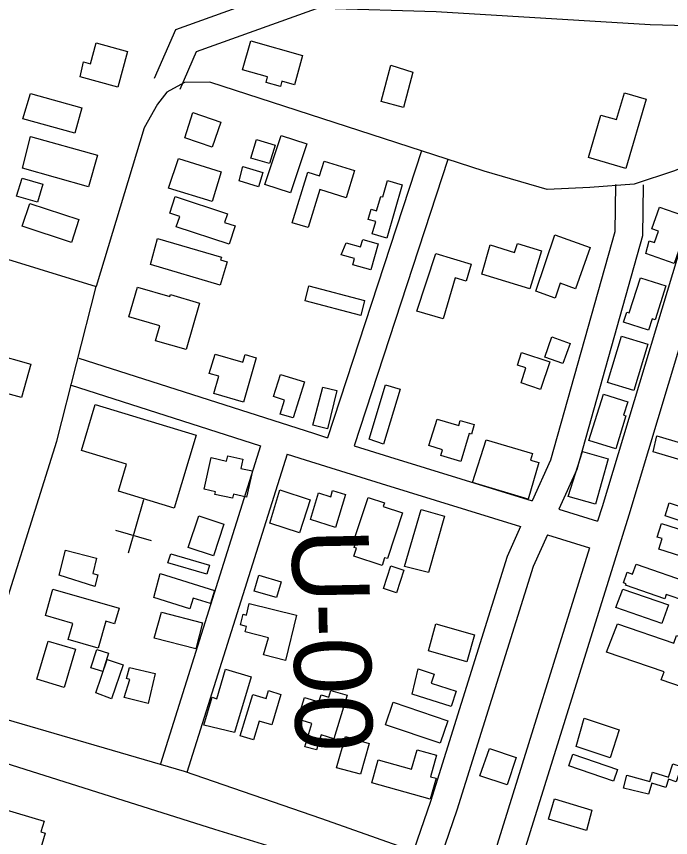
# Model space of a CAD drawing. Extents: x 3324125 to 3362000, y 600753 to 626151.
# Drawn here: x 3340066 to 3340770, y 607880 to 608764 of the extents above; entities that cross this region are included whole.
import ezdxf

# ---------------------------------------------------------------- set-up
doc = ezdxf.new("R2010")
doc.units = 0
for name, color, linetype in [('V-BLDG-OTLN', 7, 'Continuous'), ('V-LEVE-TOET', 7, 'Continuous'), ('V-RIVR-RANG-IDEN', 7, 'Continuous'), ('V-ROAD-CNTR', 7, 'Continuous'), ('V-SITE-OTLN', 7, 'Continuous')]:
    doc.layers.add(name, color=color, linetype=linetype)

msp = doc.modelspace()

# ---------------------------------------------------------------- linework, layer by layer
at = {"layer": 'V-BLDG-OTLN'}
for points in [[(3340134.5, 608698.92), (3340138.17, 608715.1), (3340145.47, 608713.1), (3340151.59, 608735.46), (3340185.35, 608726.22), (3340174.87, 608687.89)], [(3340318.34, 608737.8), (3340374.03, 608721.92), (3340365.08, 608690.53), (3340351.64, 608694.36), (3340350, 608688.63), (3340334.61, 608693.02), (3340336.31, 608698.95), (3340309.41, 608706.62)], [(3340469, 608711.7), (3340492.81, 608704.1), (3340482.79, 608666.02), (3340458.65, 608672.37)], [(3340072.69, 608653.92), (3340080.77, 608681.05), (3340136.28, 608665.67), (3340128.72, 608638.4)], [(3340681.72, 608612.01), (3340695.16, 608657.81), (3340712.07, 608652.89), (3340720.48, 608681.81), (3340743.82, 608675.02), (3340722.09, 608600.27)], [(3340255.57, 608660.44), (3340285.85, 608650.08), (3340276.7, 608623.36), (3340247.18, 608633.47)], [(3340072.12, 608600.71), (3340080.95, 608634.9), (3340152.99, 608614.69), (3340143.46, 608580.7)], [(3340378.41, 608626.98), (3340360.79, 608574.08), (3340333.34, 608583.22), (3340350.91, 608635.99)], [(3340318.28, 608611.54), (3340324.15, 608631.38), (3340344.27, 608625.43), (3340338.46, 608605.76)], [(3340240.37, 608611.02), (3340286.31, 608596.87), (3340276.41, 608564.74), (3340229.62, 608579.16)], [(3340362.6, 608541.74), (3340379.52, 608596.38), (3340392.27, 608592.43), (3340397.16, 608608.23), (3340429.82, 608598.12), (3340420.76, 608568.86), (3340392.55, 608577.59), (3340379.86, 608536.63)], [(3340309.6, 608602.48), (3340331.18, 608595.92), (3340326.56, 608580.71), (3340305.68, 608587.06)], [(3340065.92, 608570.44), (3340071.85, 608589.89), (3340094.21, 608583.41), (3340088.54, 608563.88)], [(3340465.45, 608587.18), (3340481.11, 608582.69), (3340464.68, 608525.37), (3340449.05, 608529.85), (3340452.86, 608543.17), (3340444.74, 608545.49), (3340447.86, 608556.39), (3340453.68, 608554.72), (3340458.12, 608570.21), (3340460.19, 608569.62)], [(3340080.2, 608562.47), (3340133.1, 608545.2), (3340125.1, 608520.68), (3340071.88, 608538.05)], [(3340236.64, 608569.98), (3340293.02, 608551.32), (3340289.98, 608542.13), (3340301.26, 608538.4), (3340294.73, 608518.67), (3340237.93, 608537.46), (3340241.62, 608548.63), (3340231.08, 608552.12)], [(3340743.51, 608508.85), (3340747.05, 608522.45), (3340752.77, 608520.45), (3340757.08, 608532.75), (3340750.18, 608535.17), (3340758.37, 608558.58), (3340791.26, 608547.07), (3340774.14, 608498.13)], [(3340645.74, 608528.8), (3340683.68, 608515.32), (3340667.87, 608470.83), (3340651.48, 608476.66), (3340645.82, 608460.72), (3340625.14, 608468.07)], [(3340217.61, 608525.07), (3340286.52, 608504.7), (3340285.68, 608501.87), (3340292.71, 608499.8), (3340285.3, 608474.74), (3340210, 608497)], [(3340420.73, 608520.3), (3340436.39, 608515.82), (3340438.73, 608523.98), (3340455.41, 608519.2), (3340447.33, 608491), (3340427.93, 608496.55), (3340429.89, 608503.39), (3340415.64, 608507.47)], [(3340566.88, 608486.54), (3340576.11, 608517.99), (3340602.32, 608509.96), (3340605.29, 608519.64), (3340631.3, 608511.68), (3340618.74, 608470.66)], [(3340517.28, 608508.71), (3340555.64, 608497.3), (3340550.18, 608478.93), (3340538.37, 608482.44), (3340525.25, 608438.35), (3340497.03, 608446.75)], [(3340719.68, 608434.72), (3340723.25, 608445.7), (3340725.58, 608444.95), (3340737.75, 608482.71), (3340765.28, 608473.83), (3340753.53, 608437.39), (3340750.44, 608438.39), (3340746.48, 608426.08)], [(3340376.7, 608457.6), (3340380.58, 608473.91), (3340440.76, 608458.31), (3340436.56, 608442.08)], [(3340196.16, 608472.5), (3340230.96, 608462.49), (3340231.52, 608464.44), (3340263.1, 608455.36), (3340248.67, 608405.19), (3340215.66, 608414.69), (3340220.33, 608430.95), (3340186.95, 608440.55)], [(3340642.5, 608418.89), (3340661.99, 608411.98), (3340654.26, 608390.17), (3340634.79, 608397.08)], [(3340702.43, 608369.99), (3340717.5, 608419.7), (3340745.83, 608411.02), (3340730.62, 608361.35)], [(3339985.29, 608387.32), (3339990.75, 608406.6), (3340038.22, 608393.51), (3340040.27, 608400.96), (3340081.12, 608389.69), (3340071.19, 608353.69), (3340029.03, 608365.31), (3340031.58, 608374.55)], [(3340609.85, 608402.13), (3340640.13, 608392.11), (3340630.31, 608362.45), (3340609.18, 608369.45), (3340614.53, 608385.63), (3340605.5, 608388.62)], [(3340279.69, 608400.49), (3340309.68, 608391.84), (3340311.98, 608399.82), (3340323.88, 608396.39), (3340310.15, 608348.77), (3340278.39, 608357.93), (3340283.77, 608376.61), (3340273.51, 608379.57)], [(3340363.97, 608331.67), (3340349.9, 608335.84), (3340354.64, 608350.97), (3340342.61, 608354.73), (3340350.05, 608378.53), (3340376.09, 608370.38)], [(3340445.55, 608308.9), (3340463.15, 608367.37), (3340478.94, 608362.61), (3340461.14, 608303.52)], [(3340384.9, 608323.7), (3340395.85, 608364.79), (3340410.74, 608361.26), (3340400.94, 608319.9)], [(3340682.4, 608307.34), (3340697.94, 608357.11), (3340724.17, 608348.92), (3340719.69, 608334.56), (3340722.18, 608333.79), (3340711.17, 608298.54)], [(3340150.64, 608346.18), (3340259.46, 608312.97), (3340235.5, 608234.49), (3340175.53, 608252.8), (3340184.4, 608281.86), (3340135.8, 608296.7)], [(3340518.88, 608330.28), (3340542.2, 608323.37), (3340543.83, 608328.86), (3340558.77, 608324.44), (3340555.76, 608314.27), (3340553.23, 608315.02), (3340544.26, 608284.76), (3340522.74, 608291.13), (3340524.62, 608297.48), (3340509.79, 608301.88)], [(3340571.8, 608308.14), (3340621.56, 608293.29), (3340619.45, 608286.21), (3340628.53, 608283.5), (3340616.85, 608244.36), (3340556.92, 608262.23)], [(3340751.57, 608295.32), (3340755.61, 608312.51), (3340780.92, 608304.96), (3340782.75, 608311.12), (3340850.4, 608290.95), (3340848.73, 608285.35), (3340836.79, 608288.91), (3340834.79, 608282.2), (3340864.75, 608273.27), (3340861.54, 608262.52)], [(3340267.95, 608255.13), (3340275.54, 608288.95), (3340292.05, 608285.25), (3340293.33, 608290.95), (3340309.7, 608287.28), (3340307.47, 608277.38), (3340320, 608274.57), (3340313.65, 608246.31), (3340299.51, 608249.48), (3340298.53, 608245.09), (3340279.59, 608249.34), (3340280.17, 608251.93)], [(3340659.92, 608247.12), (3340675.37, 608295.47), (3340703.18, 608287.68), (3340689.5, 608238.84)], [(3340338.78, 608218.34), (3340349.59, 608254.26), (3340382.18, 608243.59), (3340370.52, 608207.96)], [(3340382.34, 608222.28), (3340390.99, 608250.87), (3340404.2, 608246.88), (3340406.2, 608253.49), (3340420.04, 608249.31), (3340409.25, 608213.63)], [(3340460.73, 608236.39), (3340481.66, 608229.46), (3340465.35, 608180.18), (3340462.31, 608181.19), (3340459.51, 608172.71), (3340429.27, 608182.71), (3340432.11, 608191.3), (3340429.6, 608192.13), (3340433.2, 608203.01), (3340430.48, 608203.91), (3340444.43, 608246.08), (3340462.32, 608240.16)], [(3340768.73, 608240.41), (3340816.07, 608224.51), (3340811.37, 608210.53), (3340764.4, 608226.3)], [(3340250.66, 608192.01), (3340262.09, 608226.19), (3340289.26, 608217.1), (3340277.89, 608183.07)], [(3340483.87, 608171.61), (3340501.51, 608232.99), (3340526.79, 608225.73), (3340509.43, 608165.33)], [(3340760.43, 608218.13), (3340813.34, 608201.2), (3340804.99, 608175.12), (3340757.46, 608190.33), (3340761.12, 608201.74), (3340755.96, 608203.4)], [(3340111.67, 608162.42), (3340118.58, 608189.27), (3340152.11, 608180.65), (3340147.88, 608164.2), (3340153.37, 608162.79), (3340150.08, 608149.99)], [(3340232.21, 608185.34), (3340273.71, 608173.24), (3340270.83, 608163.36), (3340228.76, 608175.63)], [(3340460.92, 608147.86), (3340468.89, 608172.28), (3340483.07, 608167.65), (3340475.1, 608143.22)], [(3340733.06, 608174.25), (3340793.27, 608153.51), (3340786.65, 608134.29), (3340765.59, 608141.54), (3340763.98, 608136.87), (3340721.73, 608151.42), (3340722.32, 608153.12), (3340719.56, 608154.07), (3340723.47, 608165.43), (3340729.2, 608163.46)], [(3340220.41, 608164.06), (3340279, 608145.72), (3340274.62, 608131.73), (3340256.25, 608137.48), (3340252.68, 608126.07), (3340213.62, 608138.29)], [(3340326.71, 608162.2), (3340350.77, 608155.29), (3340345.88, 608138.25), (3340321.73, 608145.19)], [(3340105.08, 608147.42), (3340176.23, 608126.67), (3340171.39, 608110.11), (3340162.14, 608112.81), (3340153.65, 608083.69), (3340121.51, 608093.07), (3340126.5, 608110.16), (3340096.97, 608118.77)], [(3340711.25, 608127.59), (3340718.71, 608147.39), (3340767.96, 608130.29), (3340761.02, 608110.32)], [(3340331.78, 608076.48), (3340337.4, 608094.94), (3340312.21, 608101.18), (3340313.67, 608107.09), (3340306.94, 608108.75), (3340309.79, 608120.24), (3340313.48, 608119.33), (3340316.55, 608131.71), (3340367.5, 608119.1), (3340355.49, 608070.61)], [(3340221.89, 608122.59), (3340266.18, 608111.19), (3340258.93, 608083.03), (3340214.16, 608094.56)], [(3340509.59, 608080.71), (3340517.56, 608109.78), (3340559.02, 608097.93), (3340550.74, 608068.95)], [(3340713.03, 608109.86), (3340773.94, 608089.13), (3340776.69, 608097.2), (3340805.32, 608087.45), (3340796.39, 608061.23), (3340790.44, 608063.26), (3340783.12, 608041.74), (3340760.21, 608049.54), (3340763.23, 608058.4), (3340701.31, 608079.47)], [(3340087.87, 608050.49), (3340099.98, 608091.3), (3340129.46, 608082.55), (3340117.23, 608041.33)], [(3340146.04, 608062.47), (3340152.27, 608082.35), (3340165.09, 608078.33), (3340158.94, 608058.71)], [(3340168.08, 608029.06), (3340151.44, 608035.62), (3340163.63, 608071.44), (3340180.54, 608065.69)], [(3340181.67, 608030.49), (3340187.99, 608050.08), (3340184.43, 608050.94), (3340187.36, 608063.07), (3340215.2, 608056.36), (3340207.47, 608024.27)], [(3340300.6, 607992.76), (3340267.59, 608000.83), (3340276.58, 608030.8), (3340281.45, 608029.34), (3340290.95, 608061.04), (3340318.59, 608052.75)], [(3340491.92, 608034.31), (3340498.44, 608061.31), (3340515.52, 608055.85), (3340512.37, 608046.01), (3340539.41, 608037.36), (3340534.12, 608020.82)], [(3340306.88, 607989.29), (3340320.37, 608033.93), (3340334.71, 608029.6), (3340337.24, 608037.97), (3340350.63, 608033.92), (3340340.73, 608001.19), (3340327.3, 608005.25), (3340321.18, 607985)], [(3340376.33, 607977.6), (3340383.94, 608002.71), (3340368.83, 608007.29), (3340375.89, 608030.59), (3340391.6, 608025.83), (3340393.92, 608033.51), (3340402.31, 608030.97), (3340404.54, 608038.31), (3340421.99, 608033.02), (3340407.74, 607986.01), (3340393.79, 607990.24), (3340388.97, 607974.35)], [(3340530.23, 608005.65), (3340522.01, 607981.4), (3340463.33, 608001.3), (3340471.55, 608025.54)], [(3340677.08, 608008.23), (3340715.02, 607995.79), (3340705.16, 607965.72), (3340668.64, 607977.7)], [(3340410.54, 607955.02), (3340420.22, 607988.5), (3340445.75, 607981.11), (3340436.21, 607948.16)], [(3340448.56, 607938.72), (3340455.35, 607963.35), (3340491.33, 607953.25), (3340497.27, 607974.4), (3340518.08, 607968.56), (3340511.55, 607945.3), (3340517.66, 607943.58), (3340511.34, 607921.08)], [(3340564.95, 607946.07), (3340575.11, 607975.72), (3340604.03, 607966.15), (3340594.19, 607936.39)], [(3340660.85, 607957.06), (3340664.92, 607969.72), (3340713.22, 607953.05), (3340708.88, 607940.48)], [(3340746.4, 607926.48), (3340719.68, 607932.85), (3340723.09, 607947.14), (3340747.9, 607940), (3340750.87, 607950.31), (3340768.08, 607944.89), (3340772.56, 607959.15), (3340781.49, 607956.34), (3340776.33, 607939.94), (3340767.89, 607942.6), (3340765.09, 607933.7), (3340750.15, 607938.4)], [(3340021.54, 607919.4), (3340095.52, 607897.35), (3340092.12, 607885.96), (3340096.84, 607884.55), (3340089.55, 607860.08), (3340010.27, 607883.71)], [(3340679.79, 607887.2), (3340638.72, 607899.63), (3340645.36, 607921.57), (3340685.53, 607909.41)]]:
    msp.add_lwpolyline(points, close=True, dxfattribs=at)
at = {"layer": 'V-LEVE-TOET'}
msp.add_lwpolyline([(3340396.66, 608772.91), (3340517.88, 608769.28), (3340748.22, 608755.51), (3340919.67, 608750.7), (3341099.77, 608745.04), (3341298.5, 608738.12), (3341335.29, 608740.36), (3341432.67, 608752.27), (3341564.18, 608792.82), (3341762.3, 608863.83), (3341963.85, 608949.13), (3342106.58, 609009.62), (3342255.35, 609075.32), (3342427.05, 609152.33), (3342591.83, 609224.56), (3342754, 609299.38), (3342881.12, 609361.64)], dxfattribs=at)
at = {"layer": 'V-ROAD-CNTR'}
for points in [[(3338176.34, 609071.9), (3338350.5, 609000.51), (3338614.34, 608891.18), (3338770.27, 608820.42), (3338891.36, 608776.44), (3338927.81, 608763.62), (3338950.61, 608754.45), (3338978.41, 608743.71), (3339005.1, 608739.39), (3339056.12, 608731.64), (3339096.58, 608726.71), (3339168.31, 608727.57), (3339265.35, 608720.71), (3339321.95, 608718.77), (3339543.05, 608656.99), (3339833.05, 608571.35), (3340151.54, 608473.12)], [(3340214.48, 608697.7), (3340237.52, 608750.02), (3340414.58, 608814.02), (3340448.33, 608832.93)], [(3340241.93, 608685.61), (3340259.8, 608726.18), (3340427.09, 608786.65), (3340470.53, 608810.98), (3340497.28, 608823.91)], [(3341670.96, 608797.99), (3341463.64, 608734.07), (3341416.68, 608719.98), (3341357.15, 608708.3), (3341298.6, 608702.02), (3341157.75, 608704.8), (3341111.75, 608708.38), (3341051.39, 608710.38), (3341009.14, 608699.74), (3340951.39, 608675.31), (3340861.5, 608633.06), (3340774.65, 608597.78), (3340730.89, 608583.3), (3340683.44, 608579.72), (3340637.34, 608577.66), (3340569.43, 608597.25), (3340273.91, 608693.11), (3340246.75, 608693.06), (3340227.89, 608682.54), (3340217.83, 608669.65), (3340203.48, 608644.23), (3340151.54, 608473.12)], [(3340501.86, 608619.21), (3340400.8, 608310.38)], [(3340836.58, 608614.51), (3340830.17, 608575.2), (3340725.14, 608227), (3340612.22, 607864.16), (3340584.65, 607755.79), (3340548.5, 607697.84), (3340461.71, 607414.75), (3340457.94, 607401.96)], [(3340806.97, 608619.34), (3340800.88, 608581.97), (3340696.45, 608235.79), (3340691.69, 608220.48)], [(3340530.37, 608609.88), (3340429.48, 608301.55)], [(3340710.79, 608583.1), (3340710.17, 608532.25), (3340641.08, 608286.33), (3340621.21, 608242.29)], [(3340740.79, 608582.73), (3340740.12, 608527.93), (3340669.35, 608276.05), (3340650.09, 608233.35)], [(3339432.08, 606157.13), (3339565.59, 606591.71), (3339595.22, 606701.54), (3339779.91, 607255.77), (3339850.82, 607457.2), (3339938.73, 607750.37), (3339991.43, 607937.56), (3340033.26, 608065.6), (3340109.3, 608306.49), (3340151.54, 608473.12)], [(3340132.91, 608395.9), (3340385.54, 608315.09), (3340400.8, 608310.38)], [(3338095.14, 608382.36), (3338259.06, 608370.58), (3338551.7, 608360.93), (3338678.85, 608355.45), (3338759.93, 608349.79), (3338867.88, 608336.94), (3338938.4, 608324.44), (3339016.79, 608313.13), (3339100.95, 608289.9), (3339704.35, 608109.04), (3340246.41, 607951.2), (3340394.49, 607900.48), (3340541.49, 607848.38), (3340714.93, 607769.87), (3340880.14, 607681.75)], [(3340123.77, 608367.32), (3340328.77, 608301.75)], [(3338030.8, 608297.17), (3338260.61, 608280.26), (3338440.83, 608273.79), (3338606.68, 608268.33), (3338780.21, 608265.07), (3338943.38, 608261.04), (3339024.43, 608253.51), (3339134.05, 608234.55), (3339262.56, 608211.24), (3339404.79, 608161.61), (3340039.21, 607964.42), (3340279.06, 607888.89), (3340451.7, 607835.6), (3340556.03, 607801.31), (3340664.65, 607748.63), (3340802.72, 607681.71)], [(3340328.77, 608301.75), (3340220.8, 607959)], [(3340429.48, 608301.55), (3340467.44, 608289.86), (3340621.21, 608242.29)], [(3340357.34, 608292.61), (3340249.41, 607949.99)], [(3340357.34, 608292.61), (3340376.55, 608286.46), (3340458.6, 608261.2), (3340608.78, 608214.73)], [(3340650.09, 608233.35), (3340691.69, 608220.48)], [(3340608.78, 608214.73), (3340594.16, 608182.3), (3340511.74, 607918.58), (3340468.67, 607793.86), (3340374.44, 607480.62), (3340358.58, 607433.74)], [(3340637.66, 608205.79), (3340622.25, 608171.62), (3340540.24, 607909.21), (3340497.23, 607784.64), (3340403.02, 607471.49), (3340387.16, 607424.6)], [(3340637.66, 608205.79), (3340682.78, 608191.84)], [(3340682.78, 608191.84), (3340583.34, 607872.32), (3340556.73, 607767.71), (3340520.97, 607710.39), (3340432.98, 607423.39), (3340429.36, 607411.1)]]:
    msp.add_lwpolyline(points, dxfattribs=at)
at = {"layer": 'V-SITE-OTLN'}
for p, q in [((3340202.78, 608243.6), (3340186.23, 608185.93)), ((3340172.53, 608210.67), (3340210.97, 608199.64))]:
    msp.add_line(p, q, dxfattribs=at)

# ---------------------------------------------------------------- texts
at = {"layer": 'V-RIVR-RANG-IDEN'}
msp.add_text('U-00', height=83, rotation=271.10657, dxfattribs=at).set_placement((3340362.02, 608211.83))

doc.saveas('drawing.dxf')
